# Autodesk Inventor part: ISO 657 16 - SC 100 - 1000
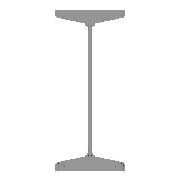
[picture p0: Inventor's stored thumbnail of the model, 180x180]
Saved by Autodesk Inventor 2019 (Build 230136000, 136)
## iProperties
_CCFamilyMember: 1
_CCFamilyDisplayName: ISO 657/16 - 1980 - Poutres en acier laminées à chaud - Partie 16: profilés en H (série métrique) - Cotes et propriétés de section
_FrameMemberDoc: Frame Member File
_Version: 15.0.0
_GetPNFromCC: 1
Created: 2018-07
Part Number: ISO 657 16 - SC 100 - 1000
Material: Acier, doux
Description: Poutres en acier laminées à chaud - Partie 16: profilés en H (série métrique) - Cotes et propriétés de section
Document SubType Name: Modeling
Standard: ISO
Designer: Fabian Perrée
Standard Revision: First edition 1980-02-15
Standards Organization: ISO
Language: fr-FR
Size Designation: SC 100
Categories: <MemberInstance><Categories><Category DisplayName="Profilés" InternalName="089c4875-fa83-4c05-b084-43b9cc11f5ed" Mnemonic="GRDR"><CategoryParameter DisplayName=
Stock Number: SC 100
Density: 7.85 g/cm^3
Appearance: Semi-poli
Mass: 19656.9 g
Surface Area: 5357.79 cm^2
Volume: 2504.06 cm^3
IsCustomPart: 1
G_W: 100,000 mm
G_H: 100,000 mm
+66B73B83-1ABF-4F18-8224-AF9602477DE0+DETAILDECOUPE1: Grugeage
+9F30C4B5-7857-4BA6-ACFD-6D0F8F96A7E8+DETAILDECOUPE2: Grugeage
G_L: 1000,000 mm
Author: Fabian Perrée
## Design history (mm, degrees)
node "Plan de départ"
node "Plan de fin"
sketch "Esquisse"
  geometry: L1 (-3, 0)-(-3, -26.266); L2 (-13.33, -38.149)-(-44.835, -42.577); L3 (-50, -48.518)-(-50, -50); L4 (-50, -50)-(0, -50); L5 (-26.5, -50)-(-26.5, -40); L6 (-61.333, 0)-(81.777, 0); L7 (0, 0)-(0, -50); L8 (0, -60)-(0, 80); L9 (3, 0)-(3, -26.266); L10 (13.33, -38.149)-(44.835, -42.577); L11 (50, -48.518)-(50, -50); L12 (50, -50)-(0, -50); L13 (-3, 0)-(0, 0); L14 (-3, 0)-(-3, 26.266); L15 (-13.33, 38.149)-(-44.835, 42.577); L16 (-50, 48.518)-(-50, 50); L17 (-50, 50)-(0, 50); L18 (50, 48.518)-(50, 50); L19 (13.33, 38.149)-(44.835, 42.577); L20 (3, 0)-(3, 26.266); L21 (50, 50)-(0, 50); L22 (0, 108)-(0, -88) reference; L23 (-89.955, 0)-(110.399, 0) reference; A1 r 6 centre (-44, 48.518) between (-50, 48.518) and (-44.835, 42.577); A2 r 6 centre (44, 48.518) between (44.835, 42.577) and (50, 48.518); A3 r 6 centre (44, -48.518) between (50, -48.518) and (44.835, -42.577); A4 r 6 centre (-44, -48.518) between (-44.835, -42.577) and (-50, -48.518); A5 r 12 centre (-15, 26.266) between (-3, 26.266) and (-13.33, 38.149); A6 r 12 centre (15, 26.266) between (13.33, 38.149) and (3, 26.266); A7 r 12 centre (15, -26.266) between (3, -26.266) and (13.33, -38.149); A8 r 12 centre (-15, -26.266) between (-13.33, -38.149) and (-3, -26.266); 14 further points
  constraints: 42 end point, 24 point on line, 17 symmetric about line, 16 point on circle, 16 tangent, 8 centre point, 6 equal radius, 4 collinear, 2 perpendicular, 12 other
  dimensions: "d1" = 10 vertical distance of L3.end L5.end (= G_T1); "d2" = 23.5 distance between parallel lines of L5 L3 (= -0.25 x G_T + 0.25 x G_W); "d3" = 3 distance between parallel lines of L1 L7 (= 0.5 x G_T); "d4" = 50 distance between parallel lines of L7 L3 (= 0.5 x G_W); "d9" = 50 distance from line of L1.start L4 (= 0.5 x G_H); "d14" = 98 deg angle of L2 L1 (= G_NG); "d15" = 6 radius of A1 (= G_ER); "d16" = 12 radius of A5 (= G_IR)
extrude "Corps" new body sketch "Esquisse" stored distance "d5" = 1000 (= G_L); taper "d6" = 0 deg
node "Driven Length"
  sketch "Sketch3"
    geometry: L1 (0, 0)-(10, 0) reference
    constraints: 2 end point, 1 horizontal
  workplane "Work Plane3"
  sketch "Sketch4"
    geometry: L1 (-2, 0)-(12, 0) reference; L2 (-2, 1000)-(12, 1000) reference
    dimensions: "d20" = 1000 distance between parallel lines of L1 L2 (derived)
node "Plan de construction4"
node "Plan de construction5"
node "Plan de construction6"
sketch "Esquisse5"
  geometry: L1 (-3, 0)-(-3, -26.266); L2 (-13.33, -38.149)-(-44.835, -42.577); L3 (-50, -48.518)-(-50, -50); L4 (-50, -50)-(0, -50); L5 (50, -50)-(0, -50); L6 (50, -48.518)-(50, -50); L7 (13.33, -38.149)-(44.835, -42.577); L8 (3, 0)-(3, -26.266); L9 (3, 0)-(3, 26.266); L10 (13.33, 38.149)-(44.835, 42.577); L11 (50, 48.518)-(50, 50); L12 (50, 50)-(0, 50); L13 (-50, 50)-(0, 50); L14 (-50, 48.518)-(-50, 50); L15 (-13.33, 38.149)-(-44.835, 42.577); L16 (-3, 0)-(-3, 26.266); A1 r 12 centre (-15, -26.266) between (-13.33, -38.149) and (-3, -26.266); A2 r 6 centre (-44, -48.518) between (-44.835, -42.577) and (-50, -48.518); A3 r 6 centre (44, -48.518) between (50, -48.518) and (44.835, -42.577); A4 r 12 centre (15, -26.266) between (3, -26.266) and (13.33, -38.149); A5 r 12 centre (15, 26.266) between (13.33, 38.149) and (3, 26.266); A6 r 6 centre (44, 48.518) between (44.835, 42.577) and (50, 48.518); A7 r 6 centre (-44, 48.518) between (-50, 48.518) and (-44.835, 42.577); A8 r 12 centre (-15, 26.266) between (-3, 26.266) and (-13.33, 38.149)
  constraints: 32 end point, 16 point on circle, 8 centre point
extrude "Extrusion2" cut sketch "Esquisse5" stored distance "d21" = 0.13; taper "d22" = 0 deg
node "Plan de construction7"
node "Plan de construction8"
node "Plan de construction9"
sketch "Esquisse6"
  geometry: L1 (-3, 0)-(-3, -26.266); L2 (-13.33, -38.149)-(-44.835, -42.577); L3 (-50, -48.518)-(-50, -50); L4 (-50, -50)-(0, -50); L5 (50, -50)-(0, -50); L6 (50, -48.518)-(50, -50); L7 (13.33, -38.149)-(44.835, -42.577); L8 (3, 0)-(3, -26.266); L9 (3, 0)-(3, 26.266); L10 (13.33, 38.149)-(44.835, 42.577); L11 (50, 48.518)-(50, 50); L12 (50, 50)-(0, 50); L13 (-50, 50)-(0, 50); L14 (-50, 48.518)-(-50, 50); L15 (-13.33, 38.149)-(-44.835, 42.577); L16 (-3, 0)-(-3, 26.266); A1 r 12 centre (-15, -26.266) between (-13.33, -38.149) and (-3, -26.266); A2 r 6 centre (-44, -48.518) between (-44.835, -42.577) and (-50, -48.518); A3 r 6 centre (44, -48.518) between (50, -48.518) and (44.835, -42.577); A4 r 12 centre (15, -26.266) between (3, -26.266) and (13.33, -38.149); A5 r 12 centre (15, 26.266) between (13.33, 38.149) and (3, 26.266); A6 r 6 centre (44, 48.518) between (44.835, 42.577) and (50, 48.518); A7 r 6 centre (-44, 48.518) between (-50, 48.518) and (-44.835, 42.577); A8 r 12 centre (-15, 26.266) between (-3, 26.266) and (-13.33, 38.149)
  constraints: 32 end point, 16 point on circle, 8 centre point
extrude "Extrusion3" cut sketch "Esquisse6" stored distance "d23" = 0.13; taper "d24" = 0 deg
body "Solid1"
other parameters: "G_W" = 100 (= G_H) [user parameter; used in 2 equation terms], "G_H" = 100 [user parameter; used in 2 equation terms], "G_T" = 6 [user parameter; used in 2 equation terms], "G_T1" = 10 [user parameter; used in 1 equation term], "G_L" = 1000 (= d20) [user parameter; used in 1 equation term], "G_ER" = 6 [user parameter; used in 1 equation term], "G_IR" = 12 [user parameter; used in 1 equation term], "G_NG" = 98 deg [user parameter; used in 1 equation term], "G_OFFSET_START" = 0 [user parameter; used in 1 equation term], "G_OFFSET_END" = 0 [user parameter; used in 1 equation term], "d17" = 0 (computed from G_OFFSET_START), "d19" = 90 deg
